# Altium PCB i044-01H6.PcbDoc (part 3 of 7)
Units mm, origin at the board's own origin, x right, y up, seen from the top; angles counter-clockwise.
Board outline 42 x 29.01 mm, 8 copper layers (Top Layer, Mid-Layer 1, Mid-Layer 2, Mid-Layer 3, Mid-Layer 4, Mid-Layer 5, Mid-Layer 6, Bottom Layer), stack 1.474 mm thick; 235 components, 197 nets, 1006 pads, 1183 vias.
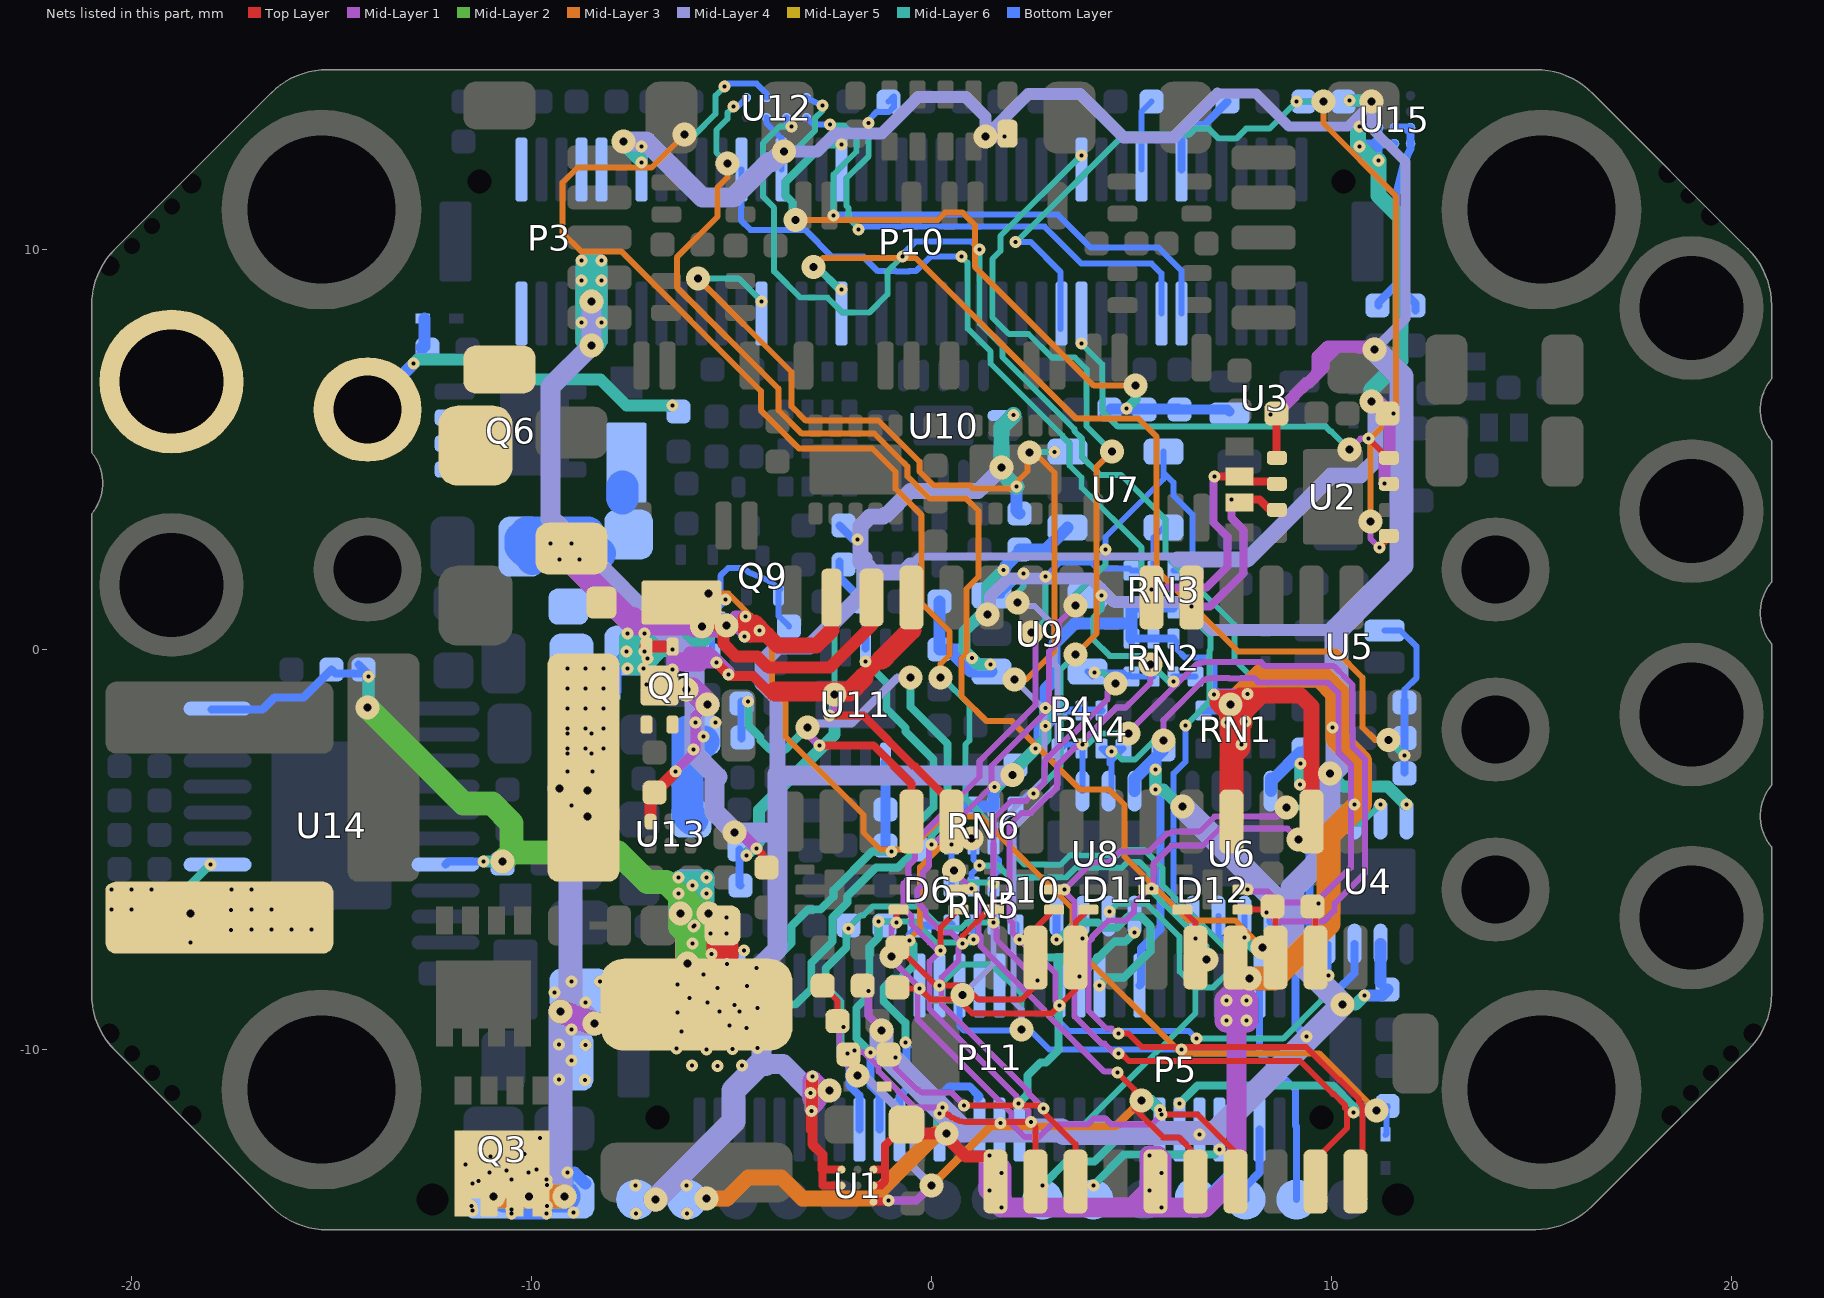
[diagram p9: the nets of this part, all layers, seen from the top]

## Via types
v1: diameter 0.3/0.3 (per signal layer), hole 0.1, Mid-Layer 6 to Bottom Layer, 515 vias
v2: diameter 0.3/0.3 (per signal layer), hole 0.1, Top Layer to Mid-Layer 1, 392 vias
v3: diameter 0.6, hole 0.2, Mid-Layer 1 to Mid-Layer 6, 276 vias

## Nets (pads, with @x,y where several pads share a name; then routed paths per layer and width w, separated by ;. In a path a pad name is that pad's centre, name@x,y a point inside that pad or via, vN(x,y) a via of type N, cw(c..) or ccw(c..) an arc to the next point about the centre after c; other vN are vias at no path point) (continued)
3.3V_D: C13.2 C16.1 C17.1 C19.1 C22.1 C26.1 D9.1 L7.2 P10.14 P11.25 P11.29 P11.46 pad.5 R47.1 R57.2 U2.5 U4.2 U4.8 U6.8 U7.1 U8.8 U9.1 U12.A2 | length 125.9
  Top Layer w0.2: v2(8.475,5.875) 8.6,5.875 C13.2@8.625,5.9 U2.5@8.625,4.775
  Mid-Layer 1 w0.2: v2(-1.58,-8.53) -1.58,-9.145 v3@-1.225,-9.5 ; v2(8.475,5.875) v2@8.533,5.875 ; v3@11.05,7.55 11.075,7.525 v3(11.075,7.5)
  Mid-Layer 1 w0.3: v3@1.35,12.9 ccw(c1.531,13.081) 1.531,12.825 v2(1.825,12.825) ; v2@8.533,5.875 8.604,5.875 9.06,6.331 9.06,6.346 9.375,6.661 9.411,6.661 9.8,7.05 9.8,7.224 10.151,7.575 10.649,7.575 10.666,7.557 v3@11.043,7.557 ; 9.62,6.905 9.65,6.935 9.65,7.325 9.907,7.582 10.982,7.582 11,7.6 v3@11.043,7.557 ; v3@11.05,7.55 v3@11.043,7.557 ; v3@11.075,7.575 11.057,7.557 v3@11.043,7.557
  Mid-Layer 3 w0.4: v3(-5.63,-13.725) -5.115,-13.725 -4.59,-13.2 -3.75,-13.2 -3.225,-13.725 -1.5,-13.725 0.125,-12.1 v3(0.375,-12.1)
  Mid-Layer 4 w0.15: v3(1.351,12.826) v3@1.351,12.948
  Mid-Layer 4 w0.2: v3(1.4,0.875) v3@1.422,0.897
  Mid-Layer 4 w0.25: 7.149,13.899 8.118,13.899 8.942,13.075 10.4,13.075 11,13.675 v3(11,13.7) 11.015,13.685 11.015,13.025 11.85,12.19 11.85,8.275 v3(11.075,7.5)
  Mid-Layer 4 w0.3: v3(-3.685,12.45) -2.864,12.45 -2.409,12.905 -1.244,12.905 -0.334,13.815 0.86,13.815 1.351,13.324 v3@1.351,12.948 ; v3(1.351,12.826) 2.415,13.89 3.719,13.89 4.799,12.81 6.06,12.81 7.149,13.899 ; v3@1.425,0.9 1.457,0.932 1.457,1.331 1.901,1.775 3.983,1.775 4.569,1.189 6.311,1.189 7.011,0.489 10.125,0.489
  Mid-Layer 4 w0.5: v3(-7.7,12.7) -7.124,12.7 -5.73,11.306 -4.954,11.306 -4.07,12.19 -3.972,12.19 -3.712,12.45 v3(-3.685,12.45)
  Mid-Layer 4 w0.6: v3(-1.25,-9.525) -1.25,-10 0.775,-12.025 ; v3(0.375,-12.1) 0.45,-12.025 0.775,-12.025 ; v3(6.275,-3.925) 9.025,-6.675 ; v3@9.925,-3.137 9.925,-5.061 9.025,-5.961 9.025,-6.675 ; v3(9.962,-3.1) 10.15,-2.912 10.15,-0.786 10.125,-0.761 10.125,0.489 11.75,2.114 11.75,6.825 v3(11.075,7.5) ; 0.775,-12.025 3.252,-12.025 3.307,-12.08 7.07,-12.08 v3(10.275,-8.875) 9.025,-7.625 9.025,-6.675
  Mid-Layer 6 w0.15: v3@-3.725,12.45 v3(-3.685,12.45) -3.441,12.45 -2.915,12.976 -2.915,13.285 -2.725,13.475 v1(-2.725,13.6)
  Mid-Layer 6 w0.3: v3(-7.7,12.7) v3@-7.7,12.619 ; v1(0.2,-11.6) 0.2,-11.925 v3(0.375,-12.1) ; v1(1.48,-0.37) 1.17,-0.37 v1(1.013,-0.212) 0.82,-0.02 0.82,0.456 1.239,0.875 v3(1.4,0.875) 1.4,1.59 v1(1.8,1.99) ; v1(5.6,-3) v1(5.6,-3.5) 5.8,-3.5 6.225,-3.925 v3(6.275,-3.925) ; v1@9.211,-2.9 v1@9.225,-2.914 ; v1(9.225,-2.85) v1@9.225,-2.914 ; v3(10.275,-8.875) 10.6,-8.875 v1(10.825,-8.65) ; v1(10.45,13.725) v3@10.975,13.725 ; v1(11.875,-3.875) 11.861,-3.875 11.411,-3.425 10.287,-3.425 v3(9.962,-3.1) 9.479,-3.1 ; v3@-7.7,12.619 -7.25,12.169 v1(-7.25,12.175) v1(-7.25,12.575) -7.275,12.575 -7.343,12.643 -7.676,12.643 v3@-7.7,12.619 ; v1@9.225,-2.914 9.411,-3.1 9.479,-3.1 ; v1@9.225,-2.914 9.225,-3.354 9.479,-3.1
  Bottom Layer w0.15: U12.A2@-3.125,13.8 v1(-2.725,13.6)
  Bottom Layer w0.2: P11.25@0.2,-12 v1(0.2,-11.6) ; P11.46@5.2,-8.4 5.241,-8.359 5.241,-7.475 5.725,-6.991 5.725,-3.625 v1(5.6,-3.5) ; U6.8@8.475,-3.538 U6.8@8.487,-3.538 ; C17.1@9.3,-2.725 C17.1@9.3,-2.5 ; v1(0.2,-11.6) 0.25,-11.6 0.25,-11.12 ; v1(0.2,-11.6) 0.2,-11.17 0.25,-11.12 ; 0.25,-11.12 0.445,-10.925 0.955,-10.925 1.15,-11.12 ; 1.15,-11.12 1.2,-11.17 1.15,-11.22 1.15,-11.12
  Bottom Layer w0.3: C26.1@0.2,1.2 L7.2@0.2,0 L7.2@0.435,0 ; v1(1.013,-0.212) v1@0.933,-0.212 ; U9.1@1.5,-0.55 0.985,-0.55 0.76,-0.325 ; v1(1.8,1.99) 1.85,2.04 1.85,2.086 2.114,2.35 2.16,2.35 2.2,2.39 C22.1@2.2,2.5 2.85,2.5 U7.1@3.4,3.05 ; U8.8@5.075,-3.538 5.075,-3.225 C19.1@5.6,-2.7 ; v1(5.6,-3.5) v1(5.6,-3) C19.1@5.6,-2.7 ; C19.1@5.685,-2.5 C19.1@5.8,-2.5 C19.1@5.6,-2.7 ; U6.8@8.487,-3.538 8.487,-3.225 8.56,-3.225 9.213,-2.572 9.225,-2.585 v1(9.225,-2.85) 9.225,-3.354 v1(9.213,-3.366) ; v1(10.825,-8.65) 11.25,-8.65 C16.1@11.4,-8.5 ; C16.1@11.225,-8.325 U4.2@11.225,-7.362 ; L7.2@0.435,0 0.76,-0.325 ; L7.2@0.435,0 0.72,0 v1@0.933,-0.212 ; 0.76,-0.325 0.873,-0.212 v1@0.933,-0.212
  other v1: -6.115,-14.095 -6.13,-13.4
3.3V_REF: P10.1
5V_D: C14.2 C21.1 C23.2 C35.2 C53.2 C56.2 L11.2 P10.7 P10.8 P10.9 P10.10 pad.4 R5.2 RN1.4 RN1.6 RN1.8 RN2.4 RN2.6 RN2.8 RN3.2 RN3.4 RN3.6 RN4.1 RN4.3 RN4.5 RN6.4 RN6.6 RN6.8 U1.A1 U1.B1 U2.3 U10.14 U13.6 U15.A1 U15.A2 U15.B1 | length 118.8
  Top Layer w0.2: v2(-4.38,-4.969) -4.225,-5.124 -4.225,-5.35 R5.2@-4.125,-5.45 ; U1.B1@-2.25,-13.4 -2.725,-13.4 -2.725,-13 U1.A1@-2.25,-13
  Top Layer w0.25: -2.98,-11.981 -2.98,-12.363 -2.725,-12.618 -2.725,-13
  Top Layer w0.3: U13.6@-7.025,-4.3 -7.025,-3.675 C35.2@-6.925,-3.575 v2(-6.4,-3.05) ; -3,-11.981 v2(-3,-11.535) v2@-3,-11.408 ; -3,-10.834 v2@-3,-11.408 ; v2@-2.975,-10.775 -2.975,-11.383 v2@-3,-11.408
  Mid-Layer 1 w0.25: v2(-6.4,-3.05) -6.4,-3.037 -5.9,-2.537 -5.9,-1.65 v3@-5.65,-1.4
  Mid-Layer 1 w0.3: v3@-5.65,-1.4 -5.65,-1.375 v3@-5.625,-1.35 ; v3@-5.55,-1.35 v3@-5.625,-1.35 ; v3@-4.8,-4.675 -4.674,-4.675 v2(-4.38,-4.969) ; v2(-3.025,-11.085) -3.025,-11.475 ccw(c-2.94,-11.475) v2(-3,-11.535) -2.836,-11.371 ccw(c-3.104,-11.103) -2.725,-11.103 -2.725,-11.075 v3@-2.725,-11.025 ; v3@10.95,6.15 v3(11,6.2) ; v2(11.325,4.15) 11.325,4.819 11.45,4.944 v2@11.45,5.95 ; 11.35,5.85 v3(11,6.2) ; v2(11.55,5.9) 11.5,5.9 v2@11.45,5.95 ; v3@-5.625,-1.35 -5.75,-1.35 -6.1,-1 -6.125,-0.975 -5.825,-0.975 -5.825,-1.15 v3@-5.625,-1.35 ; v3(11,6.2) 11.2,6.2 v2@11.45,5.95
  Mid-Layer 1 w0.5: v3(-2.55,-11.025) -2.725,-11.025 -2.975,-10.775 -2.975,-11.216 -2.921,-11.271 -2.725,-11.075 -2.699,-11.049 v3@-2.514,-11.049
  Mid-Layer 1 w0.6: v3(-6.125,-1) -6.1,-1 -5.975,-1 -5.625,-1.35 v3(-5.6,-1.375)
  Mid-Layer 4 w0.2: -0.525,2.1 -0.3,2.325 6.075,2.325
  Mid-Layer 4 w0.4: -3.85,-3.125 -3.85,-1.219 -4.225,-0.844 -4.225,-0.306 -3.844,0.075 -3.056,0.075 -1.675,1.456 -1.675,2.159 ; -1.775,2.175 -1.775,3.091 -1.541,3.325 -1.199,3.325 -1.149,3.375 -1.119,3.375 -0.528,3.966 1.166,3.966 v3(1.75,4.55) ; -1.725,2.325 -1.675,2.275 -1.675,2.159 ; -0.525,2.1 -0.7,1.925 -1.441,1.925 -1.675,2.159 ; 6.15,2.25 7.891,2.25 9.991,4.35 10.719,4.35 11.1,4.731 11.1,6.1 v3(11,6.2)
  Mid-Layer 4 w0.5: v3(-8.5,8.7) v3(-8.5,7.6) -9.529,6.571 -9.529,3.282 -5.925,-0.323 -5.925,-2.615 -5.352,-3.187 -5.425,-3.26 -5.425,-4.05 v3@-4.9,-4.575 ; v3(-4.925,-4.575) v3@-4.9,-4.575 ; -4.25,-10.26 -4.25,-7.889 -3.85,-7.489 -3.85,-4.7 ; -4.15,-10.36 -3.71,-10.36 -3.045,-11.025 v3(-2.55,-11.025) ; v3(2.025,-3.13) 2.005,-3.15 -3.825,-3.15 -3.85,-3.125 -3.85,-4.7 ; v3@-4.9,-4.575 -3.975,-4.575 -3.85,-4.7
  Mid-Layer 4 w0.6: v3(-6.905,-13.75) -4.95,-11.795 -4.95,-11.016 -4.294,-10.36 -4.15,-10.36
  Mid-Layer 6 w0.2: -8.615,8.34 -8.5,8.225
  Mid-Layer 6 w0.3: v1(1.575,-3.432) 1.643,-3.432 v1(2.6,-2.475) 2.85,-2.225 v1(2.85,-1.91) v1(2.85,-1.46) ; v1@2.011,4.17 ccw(c2.211,4.333) v1@2.049,4.133
  Mid-Layer 6 w0.4: v1(2.125,4.075) 2.106,4.075 2.049,4.133 2.011,4.17 1.75,4.431 v3(1.75,4.55) 1.75,5.563 v1@2,5.813 ; v1@10.668,13.043 10.668,12.607 v1(10.7,12.575) 11.05,12.225 v1(11.175,12.225) 11.175,11.353 11.725,10.803 11.725,7.231 11,6.506 v3(11,6.2) ; v1@2,5.813 v1(2.05,5.863) ccw(c2.291,5.622) 2,5.799 v1@2,5.813
  Mid-Layer 6 w0.8: v3@-8.5,7.75 -8.5,8.225 v3(-8.5,8.7) -8.5,9.6
  Bottom Layer w0.15: RN2.4@6.05,0.275 6.125,0.2 6.125,0.017 6.342,-0.2 6.875,-0.2 7.075,-0.4 7.075,-0.975 7.275,-1.175 7.275,-1.45 RN1.6@7.35,-1.525
  Bottom Layer w0.2: C53.2@-5.7,-2.3 C53.2@-5.5,-2.1 ; v1(1.575,-3.432) 2.1,-2.907 C21.1@2.1,-2.9 C21.1@2.175,-2.9 ; RN4.1@3.2,-1.525 RN4.3@3.75,-1.525 RN4.5@4.25,-1.525 ; RN2.8@5,0.275 RN2.6@5.55,0.275 RN2.4@6.05,0.275 ; RN3.2@5,1.025 RN3.4@5.55,1.025 RN3.6@6.05,1.025 ; RN1.8@6.8,-1.475 RN1.8@6.8,-1.525 RN1.6@7.35,-1.525 RN1.4@7.85,-1.525 ; v1(10.7,12.575) 10.775,12.65 11.05,12.65 ; v1(10.7,13.075) 10.725,13.05 U15.B1@11.175,13.05 11.175,12.925 ; 11.05,13.05 11.175,12.925 ; v1(11.175,12.225) 11.175,12.525 ; U15.A1@11.175,12.55 U15.A1@11.275,12.65 ; U15.A2@11.575,12.65 U15.A1@11.275,12.65 ; 11.05,12.65 11.175,12.525 ; 11.05,12.65 11.175,12.775 ; 11.05,12.65 U15.A1@11.175,12.65 ; 11.175,12.525 U15.A1@11.175,12.65 ; U15.A1@11.175,12.65 11.175,12.775 ; U15.A1@11.175,12.65 U15.A1@11.275,12.65 ; 11.175,12.775 11.175,12.8 ; 11.175,12.8 11.3,12.675 U15.A1@11.275,12.65 ; 11.175,12.8 11.175,12.925
  Bottom Layer w0.3: RN6.8@0.5,-3.925 RN6.6@1.05,-3.925 RN6.4@1.55,-3.925 1.55,-3.457 v1(1.575,-3.432) ; v1(2.125,4.075) 2.125,3.475 C23.2@2.2,3.4 ; C21.1@2.175,-2.9 2.7,-2.375 2.7,-2.025 2.815,-1.91 v1(2.85,-1.91) v1@2.85,-1.875 ; RN2.8@5,0.275 5,0.65 ; RN3.2@5,1.025 5,0.65 ; v1@2.85,-1.875 RN4.1@3.2,-1.525 3.135,-1.46 v1(2.85,-1.46) ; v1@2.85,-1.875 v1(2.85,-1.46) ; v1(2.85,-1.46) 2.85,-0.98 3.075,-0.755 3.075,0.148 3.577,0.65 5,0.65
  Bottom Layer w0.8: C53.2@-6.1,-2.051 -6.1,-2.7 ; L11.2@-5.975,-4.25 -6.1,-4.125 -6.1,-2.7 ; C53.2@-5.7,-2.3 -6.1,-2.7
  other v1: -7.385,-14.095 -7.4,-13.4 -5.95,-2.5 -5.7,-2.175 -5.9,-1.825 -5.4,-1.825 -8.75,8.175 -8.25,8.175 -8.75,9.225 -8.25,9.225 -8.75,9.725 -8.25,9.725
  other v2: -2.975,-10.675
5V_DCDC: C4.2 C48.1 C50.2 C57.2 L1.2 L11.1 R45.1 U14.10 U14.17 | length 52.1
  Top Layer w0.8: L1.2@-5.875,-8.875 -5.225,-8.225 C4.2@-5.225,-6.9
  Mid-Layer 2 w0.4: v3@-6.068,-6.618 v3@-6.068,-6.6
  Mid-Layer 2 w0.6: v3(-14.1,-1.45) -11.7,-3.85 -10.99,-3.85 -10.498,-4.341 -10.498,-5.073 ; v3(-10.725,-5.3) -10.498,-5.073 ; v3(-6.275,-6.6) -6.275,-6.95 -6.1,-7.125 ; v3@-6.08,-7.87 v3(-6.1,-7.85) ; v3@-6.068,-6.618 -6.068,-7.093 ; -6.068,-6.303 v3@-6.068,-6.523 ; -10.498,-5.073 -7.844,-5.073 -7.103,-5.814 -6.636,-5.814 -6.288,-6.162 -6.288,-6.303 v3@-6.068,-6.523 ; v3(-6.1,-7.85) -5.738,-7.85 v2(-5.5,-7.612) ; v3(-6.1,-7.85) -6.068,-7.818 -6.068,-7.093 ; v3(-6.1,-7.85) -6.1,-7.125 ; -6.1,-7.125 -6.068,-7.093 ; -6.068,-7.093 v3@-5.691,-6.716 ; v3@-6.068,-6.523 -6.068,-6.6 v3@-5.691,-6.6 ; v3@-6.068,-6.523 -6.062,-6.529 v3@-5.691,-6.529 ; v3@-5.691,-6.716 v3@-5.691,-6.6 ; v3@-5.691,-6.716 v3(-5.575,-6.6) v3@-5.62,-6.6 ; v3@-5.691,-6.716 -5.691,-7.421 v2(-5.5,-7.612) ; v3@-5.691,-6.6 v3@-5.691,-6.529 ; v3@-5.691,-6.6 v3@-5.62,-6.6 ; v3@-5.691,-6.529 v3@-5.62,-6.6 ; v3@-5.62,-6.6 -5.597,-6.622 -5.32,-6.9 -5.225,-6.9 -5.225,-7.337 v2(-5.5,-7.612)
  Mid-Layer 3 w0.6: v3(-6.275,-6.6) -5.945,-6.6 ; -5.945,-6.6 v3(-5.575,-6.6) -5.575,-7.325 v3(-6.1,-7.85) -6.1,-6.755 -5.945,-6.6
  Mid-Layer 4 w0.4: v3@-6.127,-6.773 -6.113,-6.762 -5.925,-6.6
  Mid-Layer 4 w0.5: v3(-6.1,-7.85) -5.738,-7.85 v2(-5.5,-7.612) ; v2(-5.5,-7.612) -5.5,-6.675 v3(-5.575,-6.6) -5.575,-7.537 v2(-5.5,-7.612)
  Mid-Layer 4 w0.6: v3(-6.1,-7.85) -6.1,-7.125 ; -6.1,-7.125 v3(-5.575,-6.6) -5.925,-6.6 v3(-6.275,-6.6) -6.113,-6.762 -6.1,-6.775 -6.1,-7.125
  Mid-Layer 5 w0.6: -6.1,-7.125 v3(-5.575,-6.6) ; -6.1,-7.125 -6.1,-6.775 v3(-6.275,-6.6) v3(-5.575,-6.6) ; -6.1,-7.125 v3(-6.1,-7.85) -5.77,-7.85 -5.575,-7.655 v3(-5.575,-6.6)
  Mid-Layer 6 w0.3: v3(-14.1,-1.45) -14.075,-1.425 v1(-14.075,-0.675) ; v1(-11.2,-5.3) v3(-10.725,-5.3)
  Mid-Layer 6 w0.4: -6.294,-6.9 -6.1,-6.9 v1@-5.9,-6.9 ; -6.1,-7.375 -5.575,-6.85 v3(-5.575,-6.6) ; -5.95,-6.625 -6.075,-6.625 -6.162,-6.712 -6.388,-6.938 v1@-6.388,-5.78 ; v1@-5.85,-6.9 v1@-5.9,-6.9 ; v3@-5.716,-6.625 -5.664,-6.573 -5.625,-6.534 v1(-5.625,-6.1) v1(-5.625,-5.7) -5.643,-5.718 -5.943,-5.718 ; v3@-5.625,-6.625 v1@-5.9,-6.9 ; v1@-6.388,-5.78 -6.3,-5.868 v1@-6.3,-6.075 ; v1@-6.388,-5.78 -6.325,-5.718 -5.943,-5.718 ; v1@-6.3,-6.075 -5.943,-5.718 ; v1@-6.3,-6.075 -6.3,-6.575 -6.325,-6.55 v1(-6.325,-6.1) v1@-6.3,-6.075
  Mid-Layer 6 w0.5: v3@-6.3,-6.575 v3(-6.275,-6.6) -5.975,-6.6 -5.95,-6.625 ; v1@-5.95,-5.968 -5.95,-6.625 ; v3@-5.716,-6.625 -5.95,-6.625 ; v3@-5.7,-6.537 v3@-5.664,-6.573
  Mid-Layer 6 w0.6: v3(-6.275,-6.6) -6.162,-6.712 -6.1,-6.775 -6.1,-6.9 -6.1,-7.375 v3(-6.1,-7.85)
  Bottom Layer w0.2: U14.10@-18,-1.5 -16.724,-1.5 -16.424,-1.2 -15.7,-1.2 R45.1@-15,-0.5 -14.9,-0.6 C48.1@-14.1,-0.6 ; C48.1@-14.325,-0.375 C48.1@-14.2,-0.5 C48.1@-14.1,-0.6 ; v1(-14.075,-0.675) -14.075,-0.625 C48.1@-14.1,-0.6 ; U14.17@-12.15,-5.375 -12.075,-5.3 v1(-11.2,-5.3) C50.2@-10.7,-5.3
  other v1: -5.95,-6.925 -5.975,-5.9 -6.325,-5.7
  other v2: -5.993,-10.4 -5.35,-10.41 -4.74,-10.4 -5.625,-10 -4.974,-9.988 -6.375,-9.975 -4.35,-9.963 -6.25,-9.55 -4.622,-9.463 -5.05,-9.4 -6.35,-9.075 -4.35,-8.963 -4.919,-8.89 -5.6,-8.825 -6.051,-8.713 -5.35,-8.454 -4.609,-8.413 -6.35,-8.378 -5.7,-8.125 -4.375,-7.959 -5.118,-7.858 -4.694,-7.525 -5.975,-7.35 -5.525,-7.1 -5.125,-7.1 -5.925,-6.9 -5.125,-6.7
5V_OUT_SUP_EN: P11.47 R54.2 R57.1 U1.C3 | length 14.3
  Top Layer w0.15: R57.1@-2.72,-8.4 -2.72,-8.411 -2.35,-8.781 R54.2@-2.35,-9.29
  Top Layer w0.2: U1.C3@-1.45,-13.8 v2@-1.158,-13.8
  Mid-Layer 1 w0.15: v2(-2.2,-9.44) -2.2,-9.481 -2.3,-9.581 -2.3,-10.2 v3(-1.85,-10.65)
  Mid-Layer 1 w0.2: v2(-1.077,-13.775) -0.375,-13.775 v3(0,-13.4)
  Mid-Layer 3 w0.2: v3(0,-13.4) 1.476,-11.924 4.601,-11.924 v3(5.25,-11.275)
  Mid-Layer 4 w0.2: v3(-1.85,-10.65) -1.675,-10.65 -0.45,-11.875 -0.45,-12.95 v3(0,-13.4)
  Mid-Layer 6 w0.3: v3(5.25,-11.275) 5.48,-11.275 v1(5.71,-11.505)
5V_SAFE: R19.2 R39.2 U15.A3 U15.B2 U15.B3 | length 6.1
  Bottom Layer w0.2: R39.2@11.175,8.6 11.175,8.675 11.625,9.125 ; U15.B2@11.575,13.05 U15.B3@11.975,13.05 U15.A3@11.975,12.65 11.975,12.525 11.825,12.2 11.625,11.4 11.625,9.125 ; 11.85,13.05 11.975,12.925 ; R19.2@12.1,8.475 12.1,8.65 11.625,9.125
+5V_OUT: C6.2 D26.2 P4.4 P4.8 P5.1 P5.9 P5.14 U1.A3 U1.B3 | length 50.9
  Top Layer w0.2: U1.B3@-1.45,-13.4 -1.268,-13.4 -1.243,-13.375 ; U1.A3@-1.45,-13 -1.158,-13 ; -1.243,-13.375 -1.158,-13.29 -1.158,-13 ; C6.2@-0.625,-11.875 -0.649,-11.875 -1.158,-12.383 -1.158,-13
  Top Layer w0.3: C6.2@-0.625,-11.875 -0.409,-12.091 0.275,-12.091 0.85,-12.666 1.45,-12.666 P5.1@1.45,-12.701 ; v2(1.45,-12.65) 1.6,-12.8 P5.1@1.6,-13.3
  Top Layer w0.4: 7.525,-1.675 7.615,-1.675 7.725,-1.675 8.25,-1.15 ; 7.725,-1.15 8.25,-1.15 ; P4.4@9.5,-4.3 9.5,-1.425 9.225,-1.15 8.25,-1.15
  Top Layer w0.6: P4.8@7.5,-4.3 7.5,-2.625 ; 7.5,-2.625 7.5,-1.56 ; 7.5,-2.625 7.675,-2.45 7.675,-1.875 7.725,-1.825 v2@7.725,-1.785 ; 7.5,-1.56 7.615,-1.675 v2@7.725,-1.785 ; 7.5,-1.56 7.25,-1.31 7.7,-1.31 7.725,-1.285 7.725,-1.675 v2@7.725,-1.785
  Mid-Layer 1 w0.3: v2(7.06,-1.12) 7.61,-1.12 7.777,-1.287 7.85,-1.36 v2(7.85,-1.8) v2@7.825,-1.825 ; v3@7.2,-1.26 7.315,-1.375 7.375,-1.435 v2(7.375,-1.825) v2@7.825,-1.825 ; v2(7.75,-2.375) 7.75,-1.9 v2@7.825,-1.825
  Mid-Layer 1 w0.5: v2(1.45,-13.517) 1.425,-13.492 v2@1.425,-13.481 ; v2@1.7,-13 1.675,-13 1.425,-12.75 v2@1.425,-13.481 ; v2@1.75,-12.975 v2(1.75,-13.083) v2@1.75,-13.806 ; 5.3,-13.805 5.75,-13.805 v2(5.75,-13.083) 5.75,-12.75 5.65,-12.65 v2(5.45,-12.65) v2(5.45,-13.517) 5.017,-13.95 ; v2(7.875,-9.275) 7.679,-9.275 7.625,-9.329 7.625,-13.161 6.836,-13.95 v2(5.75,-13.95) 5.017,-13.95 ; v2@1.425,-13.481 v2@1.75,-13.806 ; v2@1.75,-13.806 v2(1.75,-13.95) 5.017,-13.95
  Mid-Layer 1 w0.6: v3@7.315,-1.375 v3(7.475,-1.375) 7.689,-1.375 7.777,-1.287 ; 7.679,-9.275 v2(7.375,-9.275) v2(7.375,-8.775) ; v2(7.875,-9.275) v2(7.875,-8.775) v2(7.375,-8.775) ; v3(7.95,-8.225) 7.925,-8.225 v2(7.375,-8.775)
  Mid-Layer 3 w0.6: v3(7.475,-1.375) 7.525,-1.375 8.25,-0.65 9.711,-0.65 10.15,-1.089 10.15,-2.228 10.712,-2.789 10.712,-3.863 9.925,-4.65 9.925,-6.861 8.561,-8.225 v3(7.95,-8.225)
  other v2: 7.9,-1.11
+LOG_SUP: D17.2 D20.1 P4.27 R4.2 | length 22.5
  Top Layer w0.4: -4.45,0.55 v2@-4.65,0.75 ; P4.27@-2.5,1.3 -2.5,0.488 -2.888,0.1 -3.842,0.1 -4.117,0.375 ; -4.65,0.5 v2@-4.375,0.5 ; -4.65,0.5 -4.525,0.375 -4.117,0.375 ; -4.65,0.5 v2@-4.65,0.75 ; v2@-4.65,0.75 -4.65,0.775 v2@-4.425,0.55 ; v2@-4.425,0.55 v2@-4.375,0.5 ; v2@-4.425,0.55 -4.425,0.683 -4.117,0.375 ; v2@-4.375,0.5 -4.35,0.475 -4.325,0.475 -4.35,0.5 v2@-4.375,0.5
  Mid-Layer 1 w0.3: v3@-4.875,0.6 -4.65,0.6 -4.45,0.4 ; v3@-4.875,0.6 -4.675,0.4 v2(-4.675,0.325) -4.525,0.325 -4.45,0.4 ; v3@-4.875,0.6 v3(-5.125,0.6) -4.9,0.825 v2(-4.65,0.825) -4.65,0.806 -4.347,0.503 -4.45,0.4
  Mid-Layer 1 w0.6: v2(-8.8,2.25) -8.8,2.45 v2(-9,2.65) -9.033,2.683 -9.492,2.683 -7.578,0.77 -7.457,0.77 -7.335,0.647 -6.747,0.647 -6.744,0.65 -6.206,0.65 -6.203,0.647 -5.971,0.647 -5.923,0.6 -5.764,0.6 v3(-5.739,0.575) -5.714,0.6 v3(-5.125,0.6)
  Mid-Layer 2 w0.6: v3(-5.739,0.575) -5.714,0.6 v3(-5.125,0.6)
  Mid-Layer 6 w0.6: v3(-5.125,0.6) v3@-5.525,0.6 ; -7.51,-0.34 -6.786,0.384 -6.786,0.6 ; -7.51,-0.34 -7.51,0.249 -7.158,0.6 -6.786,0.6 ; -7.51,-0.34 -7.253,-0.34 -6.801,0.112 -6.013,0.112 v3@-5.525,0.6 ; -6.786,0.6 v3@-5.525,0.6
  Bottom Layer w0.2: D17.2@-7.93,-1.12 -7.853,-1.043 -7.853,-0.278 v1(-7.625,-0.05)
  other v1: -7.6,-0.475 -7.2,-0.475 -7.175,-0.05 -7.607,0.4 -7.182,0.4
  other v2: -4.3,0.475 -9.3,2.25 -9.525,2.65
+LOGIC_DCDC: C38.1 C46.2 C52.1 C54.2 C58.2 C59.2 C60.2 L9.2 Q3.5 Q3.6 Q3.7 Q3.8 Q3.9 U14.1 U14.4 | length 38.1
  Mid-Layer 1 w0.6: v3(-9.275,-9.05) v3(-8.425,-9.352) ; v3(-9.3,-3.475) -8.925,-3.85 v3(-8.6,-4.175) v3(-8.6,-3.525) v3(-9.3,-3.475)
  Mid-Layer 2 w0.6: v3(-9.275,-9.05) -8.913,-9.179 v3(-8.425,-9.352) ; v3(-9.3,-3.475) -8.925,-3.85 v3(-8.6,-4.175) v3(-8.6,-3.525) v3(-9.3,-3.475)
  Mid-Layer 3 w0.6: v3(-10.95,-13.675) v3(-9.175,-13.675)
  Mid-Layer 4 w0.6: v3(-10.95,-13.675) v3(-9.175,-13.675) -9.275,-13.575 -9.275,-9.475 ; v3(-8.425,-9.352) v3@-8.473,-9.352 ; -9.275,-9.475 v3(-9.275,-9.05) -9.025,-8.8 ; -9.275,-9.475 -9.152,-9.352 v3@-8.473,-9.352 ; -9.025,-8.8 -9.025,-4.6 v3(-8.6,-4.175) ; -9.025,-8.8 v3@-8.473,-9.352 ; v3(-8.6,-4.175) v3(-9.3,-3.475) -8.65,-3.475 v3(-8.6,-3.525) v3(-8.6,-4.175)
  Mid-Layer 5 w0.6: v3(-10.95,-13.675) v3(-9.175,-13.675)
  Mid-Layer 6 w0.2: v1(-18.525,-7.325) v3(-18.525,-6.6) -18.525,-5.875 v1(-18.025,-5.375)
  Bottom Layer w0.3: v1(-11.482,-13.35) -11.207,-13.075 v1(-11.05,-13.075) ; v1(-10.5,-14.1) v1(-9.625,-14.1) ; v1(-9.625,-13.25) -9.9,-13.25 v1(-10.075,-13.075) ; C59.2@-8.65,-13.35 -8.925,-13.075 v1(-9.1,-13.075) ; v1(-11.05,-13.075) v1(-10.075,-13.075) ; v1(-11.05,-13.075) -10.95,-13.175 v3(-10.95,-13.675) -10.675,-13.675 v1(-10.075,-13.075) ; v1(-10.075,-13.075) v1(-9.1,-13.075) ; v1(-9.1,-13.075) -9.1,-13.6 v3(-9.175,-13.675) -9.175,-13.15 v1(-9.1,-13.075)
  Bottom Layer w0.8: C58.2@-10.675,-13.675 v3(-9.175,-13.675) cw(c-9.175,-12.951) C59.2@-9.687,-13.463 ; C52.1@-8.85,-2.1 -8.792,-2.158 C52.1@-8.7,-2.25
  Bottom Layer w1: C52.1@-8.792,-2.63 C52.1@-8.792,-2.158
  other v1: -8.95,-14.075 -11.482,-14.025 -10.5,-13.25 -9.31,-10.75 -8.661,-10.764 -9,-10.275 -8.65,-9.88 -9.318,-9.875 -9,-9.5 -8.65,-8.825 -9.425,-8.575 -9,-8.3 -8.288,-8.3 -9,-3.9 -9.1,-3.05 -8.475,-3.05 -9.1,-2.6 -8.5,-2.6 -9.1,-2.1 -8.5,-2.1
  other v2: -10.5,-13.991 -11.5,-13.912 -9.607,-13.912 -9.607,-13.39 -11.325,-13.279 -10.625,-13.025 -9.871,-13 -11.65,-12.875 -11.022,-12.675 -10.175,-12.61 -9.785,-12.204
  other v3: -10.068,-13.675
+LOGIC_PROTECTED: C42.2 D20.2 D21.2 L9.1 | length 3
  Bottom Layer w0.8: C42.2@-9.816,2.425 -9.97,2.271 C42.2@-10.275,2.575 -10.275,2.775 -10.125,2.925 -8.584,2.925 ; -8.334,2.425 -8.309,2.4 -8.288,2.4 ; D21.2@-7.725,3.784 -7.725,4.076 D21.2@-7.722,4.079
+V_BUS: C1.1 C2.1 D1.2 D16.2 H2.1 P2.1 P3.S1 Q6.1 Q6.2 Q6.3 R58.1 R59.2 | length 10.4
  Mid-Layer 6 w0.3: v1(-12.95,7.15) -12.85,7.25 -11.4,7.25 -10.9,6.75 -8.27,6.75 -7.62,6.1 v1(-6.475,6.1)
  Bottom Layer w0.3: P2.1@-13.55,6.55 v1(-12.95,7.15) R58.1@-12.751,7.349 ; R58.1@-12.75,7.55 R58.1@-12.725,7.575 ; R58.1@-12.675,7.575 D16.2@-12.675,8.275
  Bottom Layer w0.44: P2.1@-14.1,6 -14.1,6.125 -14.081,6.144 P2.1@-13.694,6.531
  Bottom Layer w0.6: P2.1@-14.1,6 cw(c-13.55,6) -14.081,6.144 cw(c-13.55,6) -13.694,6.531 cw(c-13.55,6) P2.1@-13.55,6.55
  other v2: -17.51,-7.01 -17,-7 -16.5,-7 -16,-7 -15.5,-7 -17.51,-6.51 -20.5,-6.5 -20,-6.5 -17,-6.5 -16.5,-6.5 -20.5,-6 -20,-6 -19.5,-6 -17.5,-6 -17,-6 -9.1,-2.472 -8.65,-2.475 -8.2,-2.475 -9.1,-1.972 -8.65,-1.975 -8.2,-1.975 -9.1,-1.472 -8.65,-1.475 -8.2,-1.475 -9.1,-0.972 -8.65,-0.975 -8.2,-0.975 -9.1,-0.472 -8.65,-0.475 -8.2,-0.475
\ABSENC1_CS: P11.31 U8.2 U12.C2 | length 48.7
  Mid-Layer 3 w0.15: v3(-6.175,12.875) -7,12.05 -8.85,12.05 -9.225,11.675 -9.225,10.425 -8.755,9.955 -7.755,9.955 -4.266,6.466 -4.266,5.983 -3.308,5.025 -1.475,5.025 -0.9,4.45 -0.9,4.019 -0.245,3.364 -0.245,1.153 0.45,0.458 0.45,-0.133 0.225,-0.358 v3(0.225,-0.7)
  Mid-Layer 6 w0.15: v3(-6.175,12.875) -5.92,12.875 -5.4,13.395 -5.4,13.85 v1(-5.175,14.075) ; v3(0.225,-0.7) 0.267,-0.7 0.95,-1.383 0.95,-2.265 0.85,-2.365 0.85,-3.732 2.075,-4.957 2.075,-5.125 2.325,-5.375 3.225,-5.375 3.45,-5.15 4.633,-5.15 4.77,-5.012 5.33,-5.012 5.775,-5.458 5.775,-5.887 7.4,-7.512 7.4,-8.084 7.043,-8.442 6.6,-8.442 ; v1(1.73,-11.832) 1.753,-11.855 3.835,-11.855 6.6,-9.09 6.6,-8.442 ; v1(4.45,-6.55) 4.65,-6.35 5.375,-6.35 6.2,-7.175 6.2,-8.042 6.6,-8.442
  Bottom Layer w0.15: v1@-5.175,14.15 -4.375,14.15 -4.125,13.9 U12.C2@-4.125,13.8
\ABSENC2_CS: P10.28 U12.C1 | length 1.5
  Bottom Layer w0.15: U12.C1@-4.125,13.3 -4.125,13.161 -3.75,12.786 P10.28@-3.75,12
\C\O\C\O\_\M\R\E\S\E\T\: P11.57 pad.16 | length 1.9
  Bottom Layer w0.2: pad.16@7.855,-13.745 7.855,-13.42 8.2,-13.075 P11.57@8.2,-12
\ETH0_LED_LINK: P10.67 U12.A1 | length 14
  Mid-Layer 6 w0.15: v1(-2.54,13.13) -2.511,13.101 -2.176,13.101 -1.875,12.801 -1.875,12.455 -2.45,11.88 v1(-2.45,10.85)
  Bottom Layer w0.15: U12.A1@-3.125,13.3 -2.955,13.13 v1(-2.54,13.13) ; v1@-2.444,10.875 -1.595,10.875 3.159,10.875 3.984,10.05 5.675,10.05 6.25,9.475 P10.67@6.25,8.4
\ETH1_LED_LINK: P10.68 R22.2 | length 2.3
  Bottom Layer w0.2: P10.68@6.25,12 6.25,12.84 6.52,13.11 6.81,13.11 R22.2@7.4,13.7
\STO1: C18.1 P10.33 R20.1 R21.1 U5.3 | length 27.9
  Mid-Layer 3 w0.15: v3(-2.95,9.56) -2.719,9.791 -0.399,9.791 3.617,5.775 5.175,5.775 5.62,5.33 5.62,2 7.661,-0.041 10.116,-0.041 10.775,-0.7 10.775,-1.944 11.088,-2.258 v3(11.425,-2.258)
  Mid-Layer 6 w0.2: v3(-2.95,9.56) -2.857,9.56 -2.297,9 v1(-2.25,9) ; v3(11.425,-2.258) 11.817,-2.65 v1(11.825,-2.65)
  Bottom Layer w0.15: U5.3@11.325,0.475 11.725,0.475 12.126,0.074 12.126,-0.698 11.825,-0.999 R20.1@11.825,-1.275
  Bottom Layer w0.2: C18.1@11.825,-3.075 R21.1@11.825,-2.213 R20.1@11.825,-1.325 R20.1@11.825,-1.275
\STO2: C20.1 P10.34 R23.1 R24.1 U3.3 | length 19.4
  Mid-Layer 3 w0.15: v3(-3.4,10.74) 0.158,10.74 0.343,10.925 0.777,10.925 1.085,10.617 1.085,9.573 4.058,6.6 v3(5.1,6.6)
  Mid-Layer 6 w0.2: v3(-3.4,10.74) -3.477,10.817 -3.477,11.183 -3.65,11.356 -3.65,11.687 -2.712,12.625 v1@-2.3,12.625
  Mid-Layer 6 w0.25: v1(4.875,6.025) 5.1,6.25 v3(5.1,6.6)
  Bottom Layer w0.25: C20.1@4.325,5.875 4.475,6.025 v1(4.875,6.025) 6.175,6.025 R23.1@6.2,6 ; C20.1@4.5,6 R24.1@5.325,6 R23.1@6.2,6 ; U3.3@7.45,5.95 7.4,6 R23.1@6.2,6
  other v1: -2.25,12.625
ABS2_CS: U6.2 U6.3 U12.D2 | length 34
  Mid-Layer 3 w0.15: v3(-5.1,12.15) -5.1,11.81 -5.35,11.56 -5.35,10.822 -6.365,9.807 -6.365,9.063 -3.825,6.523 -3.825,5.983 -3.242,5.4 -1.426,5.4 -0.6,4.574 -0.6,4.333 -0.042,3.775 0.871,3.775 1.175,3.471 1.175,1.817 0.875,1.517 0.875,-0.092 0.75,-0.217 0.75,-1.162 1.378,-1.79 2.007,-1.79 3.717,-3.5 4.442,-3.5 4.825,-3.883 4.825,-5.175 6.425,-6.775 7.6,-6.775 v3(8.275,-7.45)
  Mid-Layer 6 w0.15: v3(-5.1,12.15) -5.375,12.425 -5.375,12.995 -5.1,13.27 -5.1,13.425 v1(-4.95,13.575)
  Mid-Layer 6 w0.3: v1(7.825,-7.2) 8.075,-7.45 v3(8.275,-7.45)
  Bottom Layer w0.15: v1(-4.95,13.575) -4.85,13.575 U12.D2@-4.625,13.8 ; U6.3@7.175,-6.662 7.175,-7.154 7.271,-7.25 7.775,-7.25 v1(7.825,-7.2) U6.2@7.825,-6.662
ABS_SPI_CS: U4.3 U12.B1 | length 37
  Mid-Layer 6 w0.15: v1(-3.5,13.075) -3.802,13.075 -4.21,12.667 -4.21,11.32 -3.935,11.045 -3.935,9.458 -3.282,8.805 -2.604,8.805 -2.225,8.425 -1.558,8.425 -1.105,8.878 -1.105,9.447 -0.775,9.777 v1@-0.775,9.835 ; v1(1.2,10) 1.2,8.159 1.775,7.584 1.775,7.31 3.575,5.51 3.575,5.464 3.758,5.281 3.758,4.825 4.216,4.366 4.739,4.366 5.849,3.256 5.849,2.355 7.575,0.629 7.575,-0.254 8.196,-0.875 9.755,-0.875 10.225,-1.345 10.225,-1.655 10.025,-1.855 v1(10.025,-1.95)
  Bottom Layer w0.15: U12.B1@-3.625,13.3 -3.625,13.2 v1(-3.5,13.075) ; v1@-0.775,9.835 -0.41,10.2 1,10.2 v1(1.2,10)
  Bottom Layer w0.2: v1@10.015,-1.901 10.015,-3.209 9.45,-3.774 9.45,-8.241 9.759,-8.55 10.114,-8.55 10.575,-8.089 U4.3@10.575,-7.362
  other v1: -0.725,9.833
ABS_TX_EN: P11.33 RN5.1 U8.3 | length 7.2
  Mid-Layer 6 w0.2: v1(2.175,-11.35) 2.4,-11.125 2.4,-10.647 2.722,-10.325 2.858,-10.325 3.175,-10.008 3.175,-7.836 3.311,-7.7 ; v1(2.2,-7.25) 2.272,-7.25 2.722,-7.7 3.311,-7.7 ; v1(3.775,-7.225) 3.775,-7.236 3.311,-7.7
  Bottom Layer w0.2: RN5.1@2.1,-6.875 2.1,-7.25 v1(2.2,-7.25) ; v1(3.775,-7.225) U8.3@3.775,-6.662
ABSENC1_CLK: P11.38 U4.4 | length 9.5
  Mid-Layer 6 w0.15: v1(6.625,-9.725) 8.792,-9.725 9.75,-8.767 9.75,-8.325 v1(9.925,-8.15)
  Bottom Layer w0.15: P11.38@3.2,-8.4 3.2,-9.3 3.434,-9.534 6.434,-9.534 v1(6.625,-9.725) ; v1(9.925,-8.15) U4.4@9.925,-7.362
ABSENC1_MISO: P11.42 U8.4 | length 5.6
  Mid-Layer 6 w0.2: v1(3.125,-7.25) 3.184,-7.25 3.609,-6.825 4.159,-6.825 4.284,-6.95 4.634,-6.95 4.909,-6.675 5.241,-6.675 5.475,-6.909 5.475,-7.541 4.816,-8.2 4.4,-8.2 v1(4.2,-8.4)
  Bottom Layer w0.2: v1(3.125,-7.25) U8.4@3.125,-6.662
ABSENC1_MOSI: P11.40 U8.1 | length 1.8
  Mid-Layer 6 w0.2: v1(3.7,-8.175) 4.575,-7.3 4.85,-7.3 v1(5.075,-7.075)
ABSENC2_CLK: P10.24 U6.4 | length 27.2
  Mid-Layer 6 w0.15: v1(0.75,9.825) 0.9,9.675 0.9,8.035 1.475,7.46 1.475,7.155 3.275,5.355 3.275,5.34 3.45,5.165 3.45,4.605 3.75,4.305 3.75,4.055 5.249,2.556 5.249,2.056 6.975,0.33 6.975,0.005 6.95,-0.02 6.95,-1.3 v1(6.35,-1.9)
  Bottom Layer w0.15: P10.24@-4.75,12 -4.75,11.06 -4.765,11.045 -4.765,10.735 -4.524,10.494 -3.159,10.494 -2.49,9.825 -1.716,9.825 -1.704,9.824 -1.341,9.46 -0.883,9.46 -0.88,9.458 -0.57,9.458 -0.567,9.46 -0.39,9.46 -0.025,9.825 v1(0.75,9.825) ; v1@6.35,-2.025 6.35,-2.8 6.05,-3.1 6.05,-6.5 6.212,-6.662 U6.4@6.525,-6.662
ABSENC2_MISO/DIGENC_1A: P10.25 P11.24 U7.3 | length 31.3
  Mid-Layer 3 w0.15: v3(-5.84,9.28) -3.5,6.94 -3.5,6.083 -3.142,5.725 -1.326,5.725 -0.3,4.699 -0.3,4.458 0.058,4.1 0.971,4.1 1.046,4.025 1.967,4.025 2.4,4.458 v3@2.4,4.9 ; v3(2.075,-0.75) 2.362,-0.75 3.075,-0.038 3.075,4.425 2.5,5 2.45,5 v3(2.45,4.925) ; v3(2.45,4.925) 2.45,4.875 2.4,4.925 v3(2.45,4.925)
  Mid-Layer 4 w0.15: v3(0.775,-8.632) 1.55,-7.857 1.55,-4.497 2.825,-3.222 2.825,-1.5 v3(2.075,-0.75)
  Mid-Layer 6 w0.15: v3(-5.84,9.28) -4.822,9.28 v1(-4.25,8.708) ; v1(-0.3,-8.475) 0,-8.775 0.557,-8.775 v3@0.737,-8.594 ; v3(2.45,4.925) 2.469,4.944 v1(3.075,4.944)
ABSENC_CLK_N: D11.5 P5.19 U4.7 | length 21.2
  Top Layer w0.15: v2@4.725,-9.65 v2(4.675,-9.6) 4.925,-9.6 5.258,-9.933 9.359,-9.933 10.186,-10.76 10.208,-10.76 10.69,-11.242 10.69,-11.311 10.738,-11.359 10.738,-11.379 10.773,-11.414 10.773,-13.127 P5.19@10.6,-13.3
  Mid-Layer 1 w0.15: v2(4.675,-9.6) 4.625,-9.6 4.5,-9.475 4.375,-9.475 3.925,-9.025 3.925,-7.312 4.009,-7.228 4.009,-7.192 4.426,-6.775 4.462,-6.775 4.851,-6.775 5.06,-6.566 5.06,-6.361 5.1,-6.321 5.1,-6.314 5.5,-5.914 v2(5.5,-5.975) 5.55,-5.925 5.55,-5.352 6.002,-4.9 6.774,-4.9 7.199,-4.475 7.517,-4.475 7.521,-4.47 8.653,-4.47 8.658,-4.475 8.9,-4.475 v3(9.175,-4.75)
  Mid-Layer 6 w0.15: v3(9.175,-4.75) 9.575,-4.35 10.736,-4.35 11.211,-3.875 v1(11.225,-3.875)
ABSENC_CLK_P: D10.5 P5.17 U4.6 | length 21.6
  Top Layer w0.15: v2(4.675,-10.1) 4.72,-10.1 v2@4.795,-10.175 ; v2@4.766,-10.117 4.932,-10.283 9.214,-10.283 10.041,-11.11 10.063,-11.11 10.34,-11.387 10.34,-11.456 10.388,-11.504 10.388,-11.964 P5.17@9.6,-12.753 ; P5.17@9.6,-13.3 P5.17@9.6,-12.753 ; P5.17@9.6,-12.731 P5.17@9.6,-12.753
  Top Layer w0.2: D10.5@3.05,-6 D10.5@3.062,-6 v2(3.325,-6)
  Mid-Layer 1 w0.15: v2@3.276,-6 3.575,-6.299 3.575,-9.17 4.255,-9.85 4.325,-9.85 4.575,-10.1 v2(4.675,-10.1) ; v2(3.325,-6) 4,-5.325 4.43,-5.325 4.708,-5.047 5.431,-5.047 5.878,-4.6 5.97,-4.6 6.02,-4.55 6.699,-4.55 7.074,-4.175 7.392,-4.175 7.397,-4.17 8.655,-4.17 v3(8.875,-3.95)
  Mid-Layer 6 w0.15: v3(8.875,-3.95) v1@10.5,-3.95
  other v1: 10.575,-3.875
ABSENC_DATA_N: D12.5 P5.18 R16.2 RN4.6 RN4.8 U8.7 | length 18.5
  Top Layer w0.15: P5.18@9.6,-7.7 R16.2@9.6,-6.5
  Mid-Layer 1 w0.15: v3(5.8,-2.275) 5.8,-1.76 6.8,-0.76 6.854,-0.76 6.894,-0.72 6.962,-0.72 6.972,-0.71 7.428,-0.71 7.438,-0.72 7.724,-0.72 7.734,-0.71 8.066,-0.71 8.181,-0.825 9.879,-0.825 9.914,-0.825 9.925,-0.836 9.925,-0.843 10.175,-1.093 10.175,-2.575 10.179,-2.575 10.487,-2.883 10.487,-5.443 9.675,-6.255 v2@9.675,-6.325 ; v2(7.9,-6) 7.95,-6.05 8.416,-6.05 8.591,-6.225 8.661,-6.225 8.761,-6.325 v2@9.675,-6.325 ; v2@9.579,-6.35 v2(9.675,-6.35) v2@9.675,-6.325
  Mid-Layer 6 w0.15: v1(4.5,-2.55) 4.562,-2.55 4.762,-2.75 5.088,-2.75 5.563,-2.275 v3(5.8,-2.275)
  Bottom Layer w0.15: U8.7@4.425,-3.538 4.5,-3.463 4.5,-2.775 ; 4.45,-2.85 4.45,-2.825 ; v1(4.5,-2.55) 4.5,-2.775 ; 4.45,-2.825 4.5,-2.775 ; 4.45,-2.825 4.45,-2.675 RN4.6@4.25,-2.475 RN4.8@4.8,-2.475 4.5,-2.775
ABSENC_DATA_P: D12.4 P5.16 R16.1 RN4.2 RN4.4 U8.6 | length 19.6
  Top Layer w0.15: D12.4@7.775,-6.5 8.45,-6.5 R16.1@8.525,-6.425 ; P5.16@8.6,-7.7 R16.1@8.6,-6.5
  Mid-Layer 1 w0.15: v3(4.925,-2.1) 4.925,-2.07 6.635,-0.36 6.689,-0.36 6.729,-0.32 6.797,-0.32 6.807,-0.31 8.231,-0.31 8.333,-0.412 10.031,-0.412 10.044,-0.425 10.079,-0.425 10.325,-0.671 10.325,-0.678 10.525,-0.878 10.525,-0.924 10.525,-2.426 10.837,-2.738 10.837,-5.588 10.075,-6.35 10.075,-6.516 9.791,-6.8 8.6,-6.8 v2(8.375,-6.575)
  Mid-Layer 6 w0.15: v1(3.775,-2.375) 3.9,-2.375 4.175,-2.1 v3(4.925,-2.1)
  Bottom Layer w0.15: RN4.2@3.2,-2.475 3.225,-2.5 3.35,-2.375 v1(3.775,-2.375) U8.6@3.775,-3.538
AN1/AN_HALL_A/VOLT_C_N: C31.2 P11.6 R33.2 U11.7 | length 15
  Mid-Layer 6 w0.2: v1(-4.8,-9.05) -4.625,-8.875 -3.397,-8.875 -3,-8.478 -3,-7.827 -2.475,-7.302 -2.475,-6.698 -2.1,-6.323 -2.1,-6.159 -1.391,-5.45 -0.834,-5.45 -0.4,-5.016 -0.4,-4.391 0.05,-3.941 0.05,-2.743 -0.65,-2.043 -0.65,-1.953 -1.123,-1.48 -1.123,-0.827 v1(-1.65,-0.3)
  Bottom Layer w0.2: R33.2@-2.3,2.2 -2.3,1.8 C31.2@-1.7,1.2 -1.65,1.15 U11.7@-1.65,0.05 U11.7@-1.65,0.025
AN1/AN_HALL_A/VOLT_C_P: C29.2 P11.4 R32.2 U11.1 | length 8.6
  Mid-Layer 6 w0.2: v1(-5.3,-9.05) v1@-5.3,-8.984 ; v1@-5.276,-8.96 -4.841,-8.525 -4.325,-8.525 -4.1,-8.3 -4.1,-7.937 -3.499,-7.336 -3.499,-6.908 -3.091,-6.5 -2.772,-6.5 -2.45,-6.178 -2.45,-6.014 -1.486,-5.05 v1(-1,-5.05)
  Bottom Layer w0.25: R32.2@-1.15,-4.9 C29.2@-1.15,-4 U11.1@-1.15,-2.825
AN1_N: P4.24 R7.2 R30.1 R38.2 | length 15.5
  Top Layer w0.2: v2@-2.8,-2.425 v2(-2.8,-2.4) -1.445,-2.4 -0.5,-3.345 P4.24@-0.5,-4.3
  Mid-Layer 1 w0.2: v3@-3.025,-2.068 -3.025,-2.175 v2(-2.8,-2.4)
  Mid-Layer 4 w0.2: v3(-3.1,-1.95) -3,-1.85 -2,-1.85 -0.85,-0.7 v3(-0.525,-0.7)
  Mid-Layer 6 w0.2: v1(-4.592,-1.3) -4.575,-1.3 -4.575,-1.895 -4.275,-2.195 -4.275,-2.266 -4.041,-2.5 -3.709,-2.5 -3.68,-2.47 -3.65,-2.5 v3(-3.1,-1.95) v3@-3.16,-1.95 ; v3(-0.525,-0.7) -0.525,-1.428 0.4,-2.353 0.4,-4.225 0,-4.625 v1(0,-4.875)
  Bottom Layer w0.2: R7.2@-4.75,-2.225 R38.2@-4.75,-1.35 R38.2@-4.75,-1.3
AN1_P: P4.22 R8.2 R34.1 R35.2 | length 15.5
  Top Layer w0.2: v2(-2.55,-1.65) -1.7,-1.65 -0.424,-2.927 -0.4,-2.927 0.5,-3.827 P4.22@0.5,-4.3
  Mid-Layer 1 w0.2: v2(-2.55,-1.65) -2.425,-1.525 v3(-2.425,-1.125)
  Mid-Layer 6 w0.15: v3(-2.425,-1.125) -2.425,0.586 -1.8,1.211 -1.8,2.7 v1(-1.85,2.75)
  Mid-Layer 6 w0.3: v1@-4.576,-5.074 -4.316,-4.814 -4.316,-4.014 -2.425,-2.124 v3(-2.425,-1.125)
  Bottom Layer w0.2: R35.2@-4.8,-5 -4.8,-5.875 R8.2@-4.775,-5.9 ; R34.1@-2.3,3.1 -1.95,2.75 v1(-1.85,2.75)
  other v1: -4.625,-5.15
AN_OUT2: P10.2
BIST_MUX/LOG_SUP_DETECT: C15.2 D25.2 P11.49 Q9.1 R1.2 R3.2 R62.2 | length 38.1
  Mid-Layer 3 w0.15: v3(-5.575,1.4) -5.075,1.4 -4.525,0.85 -4.525,0.686 -3.988,0.149 -3.988,-0.988 -3.65,-1.326 -3.65,-2.178 -1.7,-4.128 -1.7,-4.575 -1.275,-5 -0.547,-5 0.278,-4.175 1.228,-4.175 3.525,-6.472 3.525,-7.375 6.242,-10.092 9.692,-10.092 v3(11.125,-11.525)
  Mid-Layer 6 w0.2: v3(-5.575,1.4) -5.498,1.323 -5.251,1.323 -5.177,1.25 v1(-5.15,1.25) ; v1(6.2,-11.35) 6.65,-10.9 10.034,-10.9 10.55,-11.416 ; v3(11.125,-11.525) v3@11.1,-11.55 ; v3@11.15,-11.6 v3@11.1,-11.55 ; 10.55,-11.416 10.966,-11.416 v3@11.1,-11.55 ; 10.55,-11.416 v1(10.55,-11.575) 11.075,-11.575 v3@11.1,-11.55
  Bottom Layer w0.15: R1.2@-5.58,-0.14 -5.485,-0.045 -5.485,0.565 R62.2@-5.39,0.66 -5.39,0.983 v1@-5.15,1.223 ; v1@-5.15,1.24 -5.28,1.37 -5.28,1.845 -5.085,2.04 -4.68,2.04 -4.575,1.935 -4.06,1.72 Q9.1@-3.78,1.51 ; Q9.1@-3.825,1.485 -3.825,0.845 R3.2@-3.56,0.58 ; D25.2@11.35,-12.14 11.375,-12.115 11.375,-11.435 C15.2@11.4,-11.41
  Bottom Layer w0.2: v1@-5.15,1.223 v1(-5.15,1.25) ; v1(6.2,-11.35) P11.49@6.25,-11.3 ; v1(10.55,-11.575) 10.675,-11.45 11.36,-11.45 C15.2@11.375,-11.435
BRAKE_DIODE_K: D18.2 P4.25 | length 6.2
  Top Layer w0.3: D18.2@-6.25,1.175 -5.913,1.175 -5.2,0.462 -5.2,0.143 -4.882,-0.175 -4.35,-0.175 -4.075,-0.45 -2.55,-0.45 -1.475,0.625 P4.25@-1.475,0.775
BRAKE_OUT: D18.1 P4.23 Q1.1 Q1.2 Q1.5 Q1.6 Q1.8 | length 11.4
  Top Layer w0.25: v2@-5.4,-0.308 -5.046,-0.661 -4.465,-0.661 -4.076,-1.05 -3.909,-1.05
  Top Layer w0.3: D18.1@-8.25,1.111 D18.1@-8.25,1.175 ; Q1.6@-7.15,0.075 Q1.6@-7.125,0.075 Q1.5@-6.475,0.075
  Top Layer w0.4: -1.65,-0.653 -1.65,-0.593 -1.072,-0.015 -1.012,-0.015
  Top Layer w0.5: -3.909,-1.05 -2.047,-1.05 -1.7,-0.702 ; -1.247,-0.25 -1.012,-0.015 -0.5,0.497 P4.23@-0.5,1.3
  Mid-Layer 1 w0.3: v2(-6.475,-0.5) v2(-6.475,-0.5) -6.472,-0.499 -6.374,-0.4 -6.224,-0.251 -6.049,-0.075 -6.008,-0.075 ; v2(-6.475,0) -6.475,-0.401 -6.3,-0.226 ; -6.224,-0.4 -5.758,-0.4 ; v2(-5.375,-0.325) -5.758,-0.325 -6.008,-0.075 ; v2(-5.075,-0.625) -5.075,-0.55 -5.312,-0.313 -5.55,-0.075 -6.008,-0.075
  other v2: -7.128,-0.876 -7.1,-0.225
CAN_COCO_RX: P10.57 U2.4 | length 9.7
  Top Layer w0.15: v2(10.925,5.275) U2.4@11.4,4.8
  Mid-Layer 1 w0.15: v3(10.45,5) 10.725,5.275 v2(10.925,5.275)
  Mid-Layer 6 w0.15: v1(3.75,7.65) 4.274,7.126 4.274,5.961 4.66,5.575 9.858,5.575 9.983,5.45 10,5.45 v3(10.45,5)
CAN_COCO_TX: P10.55 R47.2 U2.1 | length 24.8
  Top Layer w0.15: v2(11.2,2.55) U2.1@11.465,2.815 ; U2.1@11.435,2.845 U2.1@11.465,2.815 ; U2.1@11.488,2.838 U2.1@11.465,2.815
  Mid-Layer 1 w0.15: v3(10.975,3.2) 10.975,2.775 v2(11.2,2.55)
  Mid-Layer 3 w0.15: v3(9.8,13.7) 9.8,13.153 11.61,11.343 11.61,5.918 10.975,5.283 v3@10.975,3.281
  Mid-Layer 4 w0.15: v3(10.975,3.2) v3@10.975,3.281
  Mid-Layer 6 w0.15: v1(2.1,10.19) 2.12,10.19 4.815,12.885 6.454,12.885 6.595,13.025 6.933,13.025 7.183,12.775 7.617,12.775 7.867,13.025 8.45,13.025 v1(9.125,13.7) ; v1@9.211,13.7 v3(9.8,13.7)
  Bottom Layer w0.15: v1(2.1,10.19) 2.476,10.19 3.22,9.446 P10.55@3.22,8.02
CANH: D13.1 P4.9 U2.7 | length 4.8
  Top Layer w0.2: v2(7.5,3.75) 8.202,3.75 8.477,3.475 U2.7@8.625,3.475
  Mid-Layer 1 w0.2: v2(6.5,1.075) 6.963,1.075 7.8,1.912 7.8,2.988 7.5,3.288 v2(7.5,3.75)
CANL: D14.1 P4.11 U2.6 | length 6
  Top Layer w0.2: v2(7.075,4.325) D14.1@7.7,4.325 ; D14.1@7.825,4.2 8.625,4.2 U2.6@8.625,4.125
  Mid-Layer 1 w0.2: v2(5.5,1.5) 5.55,1.55 6.873,1.55 7.4,2.077 7.4,2.823 7.05,3.173 7.05,4.3 v2(7.075,4.325)
COCO_IO5/SD_DAT3: P10.58 RN6.2 | length 20.1
  Mid-Layer 3 w0.15: v3(3.6,-0.125) 4.125,0.4 4.125,0.717 4.129,0.721 4.129,4.572 v3@4.507,4.95
  Mid-Layer 6 w0.15: v1(2.555,-3.595) 3.225,-2.925 3.225,-0.5 v3(3.6,-0.125) ; v1(3.75,12.35) 3.73,12.35 1.725,10.345 1.725,9.969 1.524,9.767 1.524,8.301 1.935,7.89 2.425,7.89 3.015,7.3 3.588,7.3 3.875,7.013 3.875,5.588 v3(4.513,4.95)
  Bottom Layer w0.15: RN6.2@2.1,-3.925 2.43,-3.595 v1(2.555,-3.595)
COCO_JTAG_TCK: P11.58 pad.17 | length 5.7
  Bottom Layer w0.17: P11.58@8.2,-8.4 8.2,-10.1 9.102,-11.002 9.102,-11.899 9.125,-11.922 pad.17@9.125,-13.745
COCO_JTAG_TDI: P11.51 pad.12 | length 4.5
  Mid-Layer 6 w0.2: v1(2.775,-13.395) 3.37,-12.8 4.075,-12.8 4.6,-12.275 6.55,-12.275 v1(6.7,-12.125)
COCO_JTAG_TDO: P11.53 pad.13 | length 3.5
  Mid-Layer 6 w0.2: v1(4.045,-13.395) 4.815,-12.625 7.075,-12.625 v1(7.2,-12.5)
COCO_JTAG_TMS: P11.55 pad.15 | length 2.3
  Bottom Layer w0.2: pad.15@6.585,-13.695 6.836,-13.695 7.7,-12.831 P11.55@7.7,-12
DIG_ENC_1B: P11.26 U9.3 | length 17.2
  Mid-Layer 4 w0.15: v3(2.15,1.175) 2.236,1.089 2.579,1.089 3.075,0.592 3.075,-0.367 3.15,-0.442 3.15,-3.375 2.05,-4.475 2.05,-8.797 2.25,-8.997 v3(2.25,-9.5)
  Mid-Layer 6 w0.15: v1(0.2,-8.4) 0.725,-7.875 1.515,-7.875 2.25,-8.61 v3(2.25,-9.5) v3@2.25,-9.675 ; v3@2.075,1.349 2.3,1.574 v1(2.3,1.9)
  Bottom Layer w0.15: U9.3@1.5,1.35 U9.3@1.726,1.35 ; U9.3@1.76,1.35 U9.3@1.726,1.35 ; v1(2.3,1.9) 2.276,1.9 U9.3@1.726,1.35
DIG_ENC_1C/AN_ENC_1C: P11.28 U6.1 | length 13.6
  Mid-Layer 6 w0.15: v1(6.25,-10) 6.35,-10.1 9.075,-10.1 9.375,-9.8 v1(9.375,-9.675)
  Bottom Layer w0.15: P11.28@0.7,-8.4 0.7,-9.412 0.813,-9.525 2.475,-9.525 2.95,-10 v1(6.25,-10)
  Bottom Layer w0.2: U6.1@8.475,-6.662 8.475,-6.8 9.1,-7.425 9.1,-9.4 v1(9.375,-9.675)
DIG_ENC_2A: P11.30
DIG_ENC_2B: P11.32
DIG_HALL_1_IN: D6.5 P5.11 RN5.4 RN6.3 | length 13.3
  Top Layer w0.15: v2(4.65,-10.574) 5.075,-10.999 5.075,-11.48 5.788,-12.194 6.176,-12.194 6.6,-12.617 P5.11@6.6,-13.3
  Top Layer w0.2: D6.5@0.725,-5.975 v2(1,-5.975)
  Mid-Layer 1 w0.15: v3@0.434,-5.525 0.544,-5.525 0.994,-5.975 v2(1,-5.975) 1.175,-6.15 1.175,-7.114 1.225,-7.164 1.225,-7.414 2.825,-9.014 2.825,-9.055 4.32,-10.55 v2@4.65,-10.55
  Mid-Layer 6 w0.15: v3@0.575,-5.6 0.791,-5.816 1.516,-5.816 v1(1.55,-5.85)
  Bottom Layer w0.15: RN5.4@1.55,-5.925 1.55,-5.651 1.686,-5.515 1.686,-5.265 1.55,-5.129 RN6.3@1.55,-4.875
  other v3: 0.559,-5.525
DIG_HALL_2_IN: D12.3 P5.12 RN5.6 RN6.5 | length 10.6
  Top Layer w0.15: D12.3@6.275,-6.5 6.6,-6.825 v2(6.6,-7.225) P5.12@6.6,-7.7
  Mid-Layer 1 w0.15: v2(6.6,-7.225) 6.6,-7.475 v3(6.875,-7.75)
  Mid-Layer 6 w0.15: v1(1.2,-5.4) 1.666,-5.4 1.966,-5.7 3.36,-5.7 3.61,-5.45 4.757,-5.45 4.895,-5.312 5.205,-5.312 5.45,-5.557 5.45,-5.987 6.875,-7.412 v3(6.875,-7.75)
  Bottom Layer w0.15: RN5.6@1.05,-5.925 1,-5.875 1,-5.6 v1(1.2,-5.4) 1.05,-5.25 RN6.5@1.05,-4.875
DIG_HALL_3_IN: D6.3 P5.13 RN5.8 RN6.7 | length 19.7
  Top Layer w0.15: v2(-0.875,-6.825) -0.875,-6.527 -0.848,-6.5 D6.3@-0.825,-6.5 ; v2(5.75,-11.625) 6.658,-11.625 7.6,-12.567 P5.13@7.6,-13.3
  Mid-Layer 1 w0.15: -1,-6.925 -1,-6.975 ; v2(-0.875,-6.825) -0.875,-6.85 -1,-6.975 ; v2(5.75,-11.625) 5.5,-11.875 4.533,-11.875 4.517,-11.875 4.516,-11.874 4.504,-11.874 4.355,-11.725 4.045,-11.725 3.895,-11.875 3,-11.875 2.686,-12.189 2.329,-12.189 2,-11.86 2,-11.595 -0.354,-9.24 -0.354,-8.396 -1,-7.75 v3(-1,-7.675) -1,-6.975
  Mid-Layer 3 w0.15: v3(-1,-7.675) -0.289,-6.964 -0.289,-5.439 0.425,-4.725 v3(1,-4.725)
  Mid-Layer 6 w0.15: v1(0.5,-4.875) 0.65,-4.725 v3(1,-4.725)
  Bottom Layer w0.15: RN5.8@0.5,-5.925 v1(0.5,-4.875)
DIG_HALL_A: C30.1 P11.17 RN5.3 | length 9.9
  Mid-Layer 6 w0.15: v1(-2.075,-6.975) -2.075,-6.949 -1.771,-6.645 -1.7,-6.645 -1.48,-6.425 -0.3,-6.425 0.25,-6.975 0.724,-6.975 0.874,-6.825 v1(1.55,-6.825)
  Mid-Layer 6 w0.2: v1(-2.1,-10.1) -2.275,-9.925 -2.275,-8.803 -2.65,-8.428 -2.65,-7.972 -2.125,-7.447 -2.125,-7.025 v1(-2.075,-6.975) ; v1@-2.075,-6.949 v1@-2.075,-6.914
  Bottom Layer w0.15: RN5.3@1.55,-6.875 v1(1.55,-6.825)
  Bottom Layer w0.2: v1@-2.05,-10.05 -2.05,-10.902 -1.8,-11.152 P11.17@-1.8,-12
DIG_HALL_B: C28.1 P11.19 RN5.5 | length 8.7
  Mid-Layer 6 w0.15: v1(-1.325,-6.8) -0.424,-6.8 0.101,-7.325 0.975,-7.325 v1(1.05,-7.25)
  Mid-Layer 6 w0.2: v1@-1.525,-10.009 v1(-1.525,-10.075) -1.875,-9.725 -1.875,-8.953 -1.55,-8.628 -1.55,-7.422 -1.325,-7.197 v1(-1.325,-6.8)
  Bottom Layer w0.15: v1(1.05,-7.25) RN5.5@1.05,-6.875
  Bottom Layer w0.2: v1(-1.525,-10.075) -1.525,-10.891 -1.3,-11.116 P11.19@-1.3,-12
DIG_HALL_C: C27.1 P11.21 RN5.7 | length 6.9
  Mid-Layer 6 w0.2: v1(-0.65,-9.825) -0.65,-9.327 -0.664,-9.327 -1.2,-8.791 -1.2,-8.459 -0.966,-8.225 -0.772,-8.225 -0.45,-7.903 -0.45,-7.375 v1(-0.55,-7.275)
  Bottom Layer w0.2: P11.21@-0.8,-12 -0.8,-11.166 -0.625,-10.991 v1@-0.625,-9.901 ; v1@-0.6,-9.926 v1@-0.625,-9.901 ; v1(-0.55,-7.275) -0.55,-7.15 C27.1@-0.3,-6.9 0.475,-6.9 RN5.7@0.5,-6.875 ; v1@-0.625,-9.901 -0.625,-9.85 v1(-0.65,-9.825) -0.65,-9.876 v1@-0.625,-9.901
ECAT_CAN_ERR/ETH_NET_LED_R: P10.64 R25.1 | length 1.8
  Bottom Layer w0.15: P10.64@5.25,12 5.25,13.45 R25.1@5.5,13.7
ECAT_CAN_RUN/ETH_NET_LED_G: P10.65 R31.1 | length 13.4
  Mid-Layer 6 w0.15: v1(-1.825,10.5) -1.825,10.53 -2.075,10.78 -2.075,11.045 -2.125,11.095 -2.125,11.78 -1.57,12.335 v1(-1.57,13.17)
  Bottom Layer w0.15: v1(-1.825,10.5) -1.75,10.575 2.825,10.575 3.75,9.65 5.5,9.65 5.75,9.4 P10.65@5.75,8.4 ; v1(-1.57,13.17) -1.57,13.24 -1.355,13.455 -1.338,13.437 -1.075,13.437 -0.944,13.569 -0.944,13.7 -0.944,13.831 R31.1@-1.075,13.7
ENC_A/DATA_IN_N: D10.3 P5.5 R13.1 RN3.5 RN3.7 U7.4 | length 32.2
  Top Layer w0.15: v2(0.775,-7.35) 0.775,-7.159 D10.3@1.434,-6.5 ; v2(0.816,-11.39) 2.675,-11.39 2.759,-11.475 v2(2.8,-11.475) 2.8,-11.564 3.6,-12.364 P5.5@3.6,-13.3 ; D10.3@1.399,-6.5 D10.3@1.434,-6.5 ; D10.3@1.65,-6.5 D10.3@1.562,-6.5 D10.3@1.434,-6.5
  Mid-Layer 1 w0.15: v2(-0.9,-10.2) -0.9,-10.461 -0.361,-11 -0.325,-11 -0.25,-11.075 0.501,-11.075 v2(0.816,-11.39) ; v2@0.775,-7.264 v2(0.775,-7.35) ; v2@2.775,-11.4 2.733,-11.4 2.425,-11.092 2.425,-11.038 0.25,-8.863 0.25,-8.198 0.675,-7.773 0.675,-7.45 v2(0.775,-7.35) ; v2(2.8,-11.475) v2@2.8,-11.425 ; v3(3.6,1.1) 3.175,0.675 3.175,0.191 2.938,-0.046 2.938,-1.475 1.5,-2.913 1.5,-3.422 -0.06,-4.982 -0.06,-5.41 -0.22,-5.57 -0.22,-5.865 -0.35,-5.995 -0.35,-6.305 -0.22,-6.435 -0.22,-6.455 -0.15,-6.525 -0.15,-6.649 0.276,-7.075 0.5,-7.075 v2(0.775,-7.35)
  Mid-Layer 6 w0.15: v3(3.6,1.1) 3.6,1.373 4.35,2.123 v1(4.35,2.5)
  Bottom Layer w0.15: v1(4.35,2.5) 4.35,2.817 5.8,4.267 5.8,4.423 ; U7.4@5.8,4.95 5.8,4.423 ; RN3.5@6.05,1.975 RN3.7@6.6,1.975 6.525,2.05 6.525,3.375 6.05,3.85 6.05,4.173 5.8,4.423
ENC_A/DATA_IN_P: D6.4 P5.3 R13.2 RN3.1 RN3.3 U7.5 | length 28.8
  Top Layer w0.15: v2(0.225,-7.525) 0.225,-6.958 0.221,-6.954 D6.4@0.675,-6.5 ; v2@0.292,-11.511 ccw(c0.943,-10.965) 0.943,-11.814 v2(2.484,-11.814) 2.6,-11.93 P5.3@2.6,-13.3
  Mid-Layer 1 w0.15: v2(-1.925,-10.025) -1.896,-10.054 -1.704,-10.054 -1.325,-10.433 -1.325,-10.545 -0.42,-11.45 v2(0.276,-11.45) ; -0.052,-7.325 -0.039,-7.325 ; v2@2.425,-11.825 2.425,-11.517 2.125,-11.217 2.125,-11.162 -0.05,-8.987 -0.05,-7.8 v2(0.225,-7.525) 0.175,-7.475 0.111,-7.475 -0.039,-7.325 ; v3@2.54,0.32 2.6,0.26 2.6,-1.388 1.2,-2.788 1.2,-3.185 -0.41,-4.795 -0.41,-5.228 -0.57,-5.388 -0.57,-5.72 -0.7,-5.85 -0.7,-6.45 -0.72,-6.45 -0.5,-6.67 -0.5,-6.864 -0.039,-7.325
  Mid-Layer 6 w0.15: v3@2.54,0.32 2.6,0.38 2.6,0.5 2.85,0.75 v1(2.85,1.825)
  Bottom Layer w0.15: v1(2.85,1.825) 3.2,2.175 4.003,2.175 4.153,2.025 4.95,2.025 RN3.1@5,1.975 RN3.3@5.55,1.975 5.55,2.8 U7.5@5.8,3.05
  other v3: 2.5,0.425
ENC_B_IN_N: D11.3 P5.6 R12.1 RN2.1 RN2.3 U9.4 | length 22.2
  Top Layer w0.15: R12.1@-0.825,-8.475 -0.295,-8.475 -0.024,-8.746 0.671,-8.746 1.025,-9.1 2.996,-9.1 3.6,-8.496 P5.6@3.6,-7.7 3.6,-6.819 D11.3@3.919,-6.5
  Mid-Layer 1 w0.15: v2(3.2,-8.9) 3.1,-8.8 3.1,-8.314 3.1,-8.089 2.836,-7.825 2.766,-7.825 2.75,-7.809 2.75,-7.807 2.025,-7.082 2.025,-6.832 1.975,-6.782 1.975,-6.767 1.95,-6.742 1.95,-4.388 2.254,-4.083 2.483,-4.083 2.938,-3.629 2.961,-3.629 3.136,-3.453 3.136,-3.205 3.135,-3.203 3.135,-2.898 3.583,-2.45 3.617,-2.45 4.617,-1.45 4.849,-1.45 5.475,-0.824 v3@5.475,-0.458 ; v3@5.392,-0.375 v3@5.475,-0.458 ; v3(5.475,-0.375) v3@5.475,-0.458
  Mid-Layer 6 w0.15: v1(4.25,1.35) 4.25,1.008 4.05,0.808 4.05,0.25 4.454,-0.154 5.254,-0.154 v3(5.475,-0.375) 5.69,-0.59 5.705,-0.575 5.93,-0.8 v1(6.05,-0.8)
  Bottom Layer w0.15: RN2.3@6.05,-0.675 RN2.1@6.6,-0.675
ENC_B_IN_P: D10.4 P5.4 R12.2 RN2.5 RN2.7 U9.5 | length 18.2
  Top Layer w0.15: R12.2@-0.85,-7.425 0.121,-8.396 0.816,-8.396 1.17,-8.75 2.25,-8.75 2.6,-8.4 P5.4@2.6,-7.7 2.6,-6.963 D10.4@3.062,-6.5
  Mid-Layer 1 w0.15: v2(2.65,-8.275) 2.35,-7.975 2.35,-7.973 1.625,-7.248 1.625,-6.998 1.575,-6.948 ; v3(4.6,-0.85) 4.4,-1.05 4.4,-1.242 3.492,-2.15 3.458,-2.15 2.835,-2.774 2.835,-2.933 2.825,-2.943 2.825,-3.318 2.359,-3.783 1.989,-3.783 1.55,-4.222 1.55,-6.907 ; 1.55,-6.907 1.55,-6.923 1.575,-6.948 ; 1.55,-6.907 1.575,-6.932 1.575,-6.948
  Mid-Layer 6 w0.15: v1(4.075,-0.575) 4.274,-0.575 4.278,-0.579 4.304,-0.579 4.4,-0.675 4.412,-0.663 v3(4.6,-0.85)
  Bottom Layer w0.15: U9.5@3.9,-0.55 4.025,-0.675 U9.5@4.125,-0.575 ; v1(4.075,-0.575) U9.5@4.125,-0.575 ; RN2.5@5.55,-0.675 RN2.7@5,-0.675 4.95,-0.625 4.9,-0.675 4.8,-0.575 U9.5@4.125,-0.575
